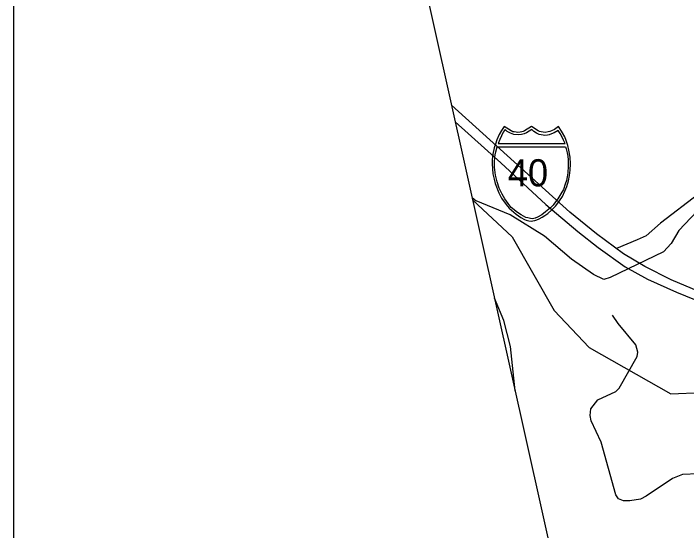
# Model space of a CAD drawing. Extents: x 1113032 to 1302912, y 664689 to 832535.
# Drawn here: x 1147669 to 1152008, y 717027 to 720361 of the extents above; entities that cross this region are included whole.
import ezdxf

# ---------------------------------------------------------------- set-up
doc = ezdxf.new("R2010")
doc.units = 0
for name, color, linetype in [('Exist Boundary Political CountyLine', 7, 'Continuous'), ('Exist Hydrographic Creek Single Shore', 7, 'Continuous'), ('Exist Hydrographic Misc Water Feature', 7, 'Continuous'), ('Exist Road Non-System Type 51', 7, 'Continuous'), ('Exist Road Primary Interstate Divided Center Attributed', 7, 'Continuous'), ('Exist Road Primary Interstate Shield CELL', 7, 'Continuous'), ('Exist Road Primary Interstate Shield Number Label', 7, 'Continuous'), ('Map Preparation Inset Cut Line', 7, 'Continuous')]:
    doc.layers.add(name, color=color, linetype=linetype)

msp = doc.modelspace()

# ---------------------------------------------------------------- linework, layer by layer
at = {"layer": 'Exist Boundary Political CountyLine'}
msp.add_lwpolyline([(1148404.8, 729149.7), (1156119.1, 694505), (1156385.7, 693318.6), (1156931.2, 691025.8), (1157283.7, 689488.8), (1157952.7, 686675.9), (1158627.6, 683719.1), (1158926.2, 682391.3), (1158990.6, 682053.6), (1159297.9, 680748.3), (1159630.3, 679269.8), (1159949.4, 677817.9), (1160303.4, 676324.9), (1160338.1, 676139.7)], dxfattribs=at)
at = {"layer": 'Exist Hydrographic Creek Single Shore'}
msp.add_lwpolyline([(1150629.8, 719157.2), (1150884.4, 718920.2), (1151154.4, 718445.4), (1151381.4, 718207.8), (1151906.4, 717908.5), (1152107.5, 717917.6), (1152439.5, 718160.4), (1152516.5, 718240.9), (1152631.4, 718455.2), (1152707.5, 718502.9), (1153282.4, 718484.9), (1153533.4, 718519.2), (1153911.4, 718626.5), (1154190.4, 718768.7), (1154277.4, 718865.3), (1154394.4, 719171.5), (1154397.4, 719296.2), (1154560.4, 719726.3), (1154671.5, 719848.7), (1154944.5, 720056.6), (1155181.4, 720176.6), (1155571.4, 720690.7), (1155665.4, 720770.8), (1155934.5, 720870.5)], dxfattribs=at)
at = {"layer": 'Exist Hydrographic Misc Water Feature'}
msp.add_line((1150626.1, 719174), (1150651.7, 719152.2), dxfattribs=at)
for points in [[(1152115.9, 719126.1), (1151959.2, 718961), (1151908.8, 718878.3), (1151859.2, 718823.5), (1151516.4, 718658.9), (1151474, 718646.6), (1151408.9, 718678.3), (1151267.5, 718776.3), (1151091.7, 718925.1), (1150871.4, 719063.2), (1150651.7, 719152.2)], [(1150903.7, 717927.1), (1150873.4, 718213.1), (1150830, 718380.5), (1150770.6, 718525)]]:
    msp.add_lwpolyline(points, dxfattribs=at)
at = {"layer": 'Exist Road Non-System Type 51'}
for points in [[(1154488.5, 722014.4), (1154358.8, 721888.7), (1154297.4, 721802.6), (1154242.8, 721696.8), (1154181.4, 721617.3), (1154065.4, 721458.5), (1154006.4, 721411.6), (1153976.6, 721306.3), (1153792.4, 721140.9), (1153608.1, 720909.3), (1153423.9, 720677.7), (1153217.1, 720343.9), (1153106.1, 720243.1), (1153052.5, 720188.4), (1153014.9, 720131.7), (1152801.8, 719963.3), (1152678, 719826.9), (1152467.7, 719538.7), (1152088, 719199), (1151840.3, 719008), (1151748.1, 718926.5), (1151689.9, 718901.9), (1151556.3, 718845.4)], [(1152082.7, 717392.2), (1151982.5, 717389), (1151918, 717362.7), (1151748.6, 717247.6), (1151711.8, 717228.6), (1151643.6, 717218.5), (1151601.6, 717217.7), (1151569.7, 717230.5), (1151552.5, 717257.1), (1151458.2, 717595.7), (1151394, 717733.9), (1151386.8, 717768.2), (1151392.3, 717812.1), (1151435.8, 717870.6), (1151551.4, 717923.4), (1151574.2, 717945), (1151689.9, 718149.8), (1151694.7, 718177.6), (1151682.2, 718224.1), (1151567.7, 718361.3), (1151531.4, 718416.5)]]:
    msp.add_lwpolyline(points, dxfattribs=at)
at = {"layer": 'Exist Road Primary Interstate Divided Center Attributed'}
for points in [[(1155365.5, 718370.8), (1154670.2, 718363.7), (1154154.5, 718371.9), (1153212.8, 718362.1), (1153014.8, 718370.2), (1152778.6, 718389.8), (1152565.1, 718422.4), (1152451.1, 718445.2), (1152288.2, 718492.5), (1152086.9, 718567.5), (1151909.3, 718644.1), (1151739.9, 718728.8), (1151602.2, 718812), (1151427.9, 718939.1), (1151255.2, 719079.3), (1150493.2, 719770.9)], [(1150517.1, 719663.4), (1150812, 719398.8), (1151100.4, 719128.2), (1151307.3, 718955.4), (1151437.7, 718851.1), (1151613.6, 718727.2), (1151756.2, 718647.3), (1151943.6, 718564.2), (1152176.5, 718469.7), (1152363.1, 718404.5), (1152483.7, 718375.1), (1152648.5, 718337.7), (1152846.9, 718312.5), (1153080.5, 718300), (1153261.4, 718292.4), (1153469.9, 718300), (1153723.6, 718302.5), (1154090.3, 718295), (1154662.1, 718305), (1155654.6, 718300.8)]]:
    msp.add_lwpolyline(points, dxfattribs=at)
at = {"layer": 'Exist Road Primary Interstate Shield CELL'}
for points in [[(1151008.4, 719022.4), (1151017.9, 719023.3), (1151030.6, 719025.8), (1151043, 719029.8), (1151057.1, 719036.1), (1151078, 719047.6), (1151094.7, 719057.4), (1151114.1, 719070.4), (1151140.2, 719094.1), (1151166.2, 719121.6), (1151189.2, 719152.6), (1151207.5, 719181.6), (1151223.5, 719214.8), (1151237, 719245.7), (1151247.7, 719281), (1151254.7, 719315.2), (1151258.3, 719350.9), (1151260.7, 719390.5), (1151258, 719435), (1151250.2, 719480.6), (1151243, 719509), (1151231.9, 719542.9), (1151222.9, 719564.6), (1151202.1, 719603), (1151183.3, 719632.6), (1151156.1, 719613.4), (1151138.4, 719604), (1151127.5, 719599.1), (1151116.4, 719597), (1151095.9, 719594.5), (1151083, 719595), (1151071, 719597.7), (1151060.9, 719599.9), (1151052.7, 719604), (1151008.4, 719632.6), (1150964.1, 719604), (1150954.9, 719599.7), (1150945.4, 719597.7), (1150936.2, 719595.2), (1150921.1, 719594.5), (1150909.5, 719594.8), (1150897.6, 719597), (1150888.3, 719598.9), (1150877.7, 719604), (1150832.6, 719632.6), (1150814.9, 719606.9), (1150800.4, 719581.5), (1150785.1, 719545.6), (1150775.5, 719517.7), (1150768.7, 719494.9), (1150760.4, 719452.9), (1150756.1, 719416.3), (1150755.3, 719390.5), (1150760, 719326), (1150767.1, 719291.6), (1150774.3, 719263.8), (1150798.2, 719203.8), (1150816.1, 719170.2), (1150831.5, 719146), (1150853.1, 719118.9), (1150864.8, 719105.9), (1150909.6, 719066.7), (1150939.5, 719046.3), (1150963.4, 719033.4), (1150974.7, 719029.1), (1150992.3, 719024.2)], [(1150838, 719611.9), (1150827, 719594.9), (1150814.3, 719572.1), (1150804.2, 719548.4), (1150793.8, 719522.3), (1151225.4, 719522.1), (1151215.3, 719544.5), (1151204.6, 719567.1), (1151193.3, 719587.6), (1151179.6, 719607.5), (1151155.4, 719592.3), (1151137.8, 719584), (1151123.6, 719579.1), (1151111.6, 719576.4), (1151093, 719574.9), (1151084.7, 719575.4), (1151058.8, 719581.3), (1151041.2, 719588.4), (1151024.5, 719599.6), (1151011, 719612.3), (1150976.8, 719591.6), (1150961.7, 719584.9), (1150944.2, 719580.5), (1150925.1, 719578.1), (1150895.7, 719581.3), (1150872.6, 719589.2), (1150852.7, 719599.6)], [(1151227.9, 719500.8), (1151232.6, 719488.6), (1151238.9, 719461.6), (1151242.3, 719440.7), (1151245.7, 719416.8), (1151244.5, 719375.6), (1151242.5, 719333), (1151238.6, 719307.8), (1151233.4, 719284.9), (1151226.2, 719259.4), (1151214.7, 719225.6), (1151198.8, 719197), (1151178.9, 719165.1), (1151157.4, 719137.3), (1151148.1, 719125.7), (1151130.4, 719107), (1151098.1, 719081.2), (1151074.6, 719063.6), (1151046.5, 719046.9), (1151032.1, 719040.6), (1151015.5, 719037.1), (1151001.8, 719038), (1150985.1, 719042.5), (1150971.7, 719046.1), (1150942.3, 719062.1), (1150918.4, 719078), (1150878.6, 719110.6), (1150857.2, 719135.7), (1150837.1, 719165.1), (1150819.3, 719195.2), (1150800.2, 719234.9), (1150786.7, 719274.8), (1150777, 719317.9), (1150770.3, 719370.5), (1150769.6, 719402.6), (1150771.6, 719433.4), (1150774.5, 719449.6), (1150778.4, 719469.6), (1150786.3, 719500.6)]]:
    msp.add_lwpolyline(points, close=True, dxfattribs=at)
at = {"layer": 'Map Preparation Inset Cut Line'}
msp.add_lwpolyline([(1223351.7, 748878.2), (1147668.5, 748878.2), (1147668.5, 704629.7), (1208143, 704629.7), (1208143, 720169.6), (1223351.7, 720169.6)], close=True, dxfattribs=at)

# ---------------------------------------------------------------- texts
at = {"layer": 'Exist Road Primary Interstate Shield Number Label'}
msp.add_text('40', height=175, dxfattribs=at).set_placement((1150855.6, 719246.2))

doc.saveas('drawing.dxf')
